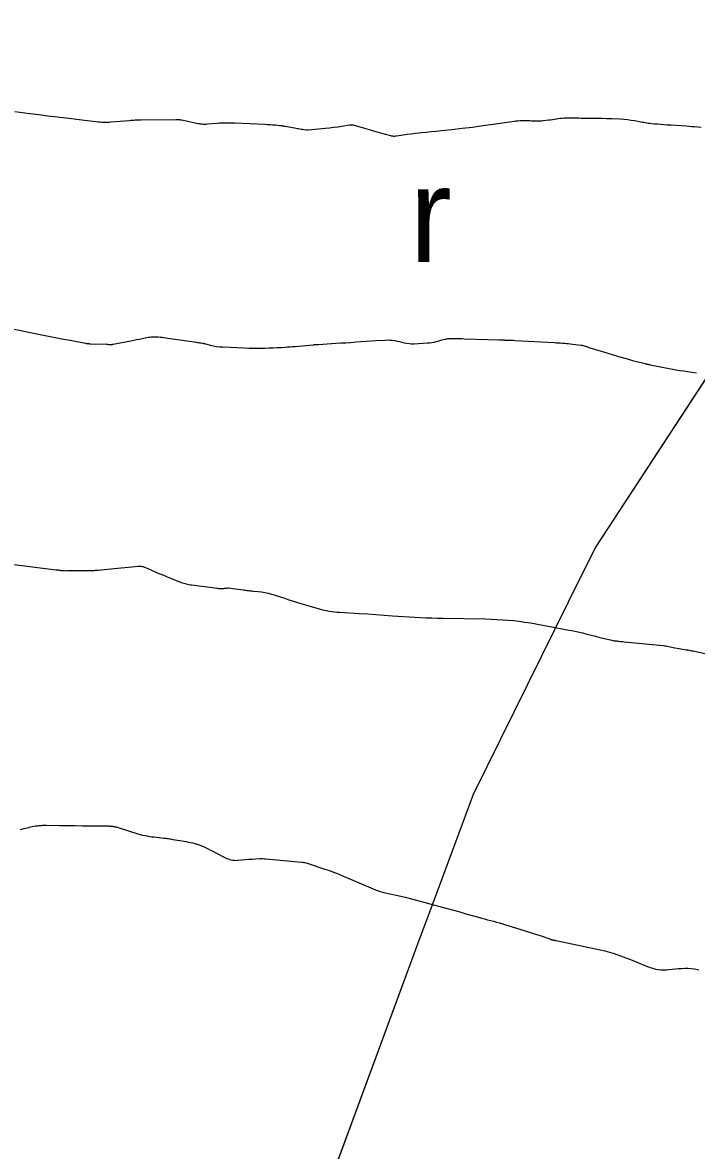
# Model space of a CAD drawing. Extents: x -629976 to -626966, y -1086511 to -1082952.
# Drawn here: x -628543.5 to -628393.8, y -1086175.2 to -1085924.7 of the extents above; entities that cross this region are included whole.
import ezdxf

# ---------------------------------------------------------------- set-up
doc = ezdxf.new("R2010")
doc.units = 0
for name, color, linetype in [('01_OBVOD PÚ', 7, 'Continuous'), ('01_SPRÁV_HRANICE', 7, 'Continuous'), ('01_VRSTEVNICE', 7, 'Continuous'), ('02_KULTURY STAV', 7, 'Continuous'), ('04_ZPF_OP_ORGAN', 7, 'Continuous')]:
    doc.layers.add(name, color=color, linetype=linetype)

msp = doc.modelspace()

# ---------------------------------------------------------------- linework, layer by layer
at = {"layer": '01_OBVOD PÚ'}
msp.add_lwpolyline([(-628341.94, -1085906.1), (-628364.43, -1085957.53), (-628376.86, -1085981.07), (-628416.21, -1086041.23), (-628422.26, -1086053.45), (-628443.41, -1086096.14), (-628453.2, -1086122.49), (-628455.25, -1086128.01), (-628487.12, -1086214.31), (-628510.82, -1086282.32), (-628525.65, -1086314.27), (-628531.32, -1086323.89), (-628534.4, -1086329.12), (-628536.6, -1086332.86), (-628546.36, -1086361.96)], dxfattribs=at)
at = {"layer": '01_SPRÁV_HRANICE'}
for p, q in [((-628376.86, -1085981.07), (-628416.21, -1086041.23)), ((-628416.21, -1086041.23), (-628422.26, -1086053.45)), ((-628422.26, -1086053.45), (-628443.41, -1086096.14)), ((-628443.41, -1086096.14), (-628453.2, -1086122.49)), ((-628453.2, -1086122.49), (-628455.25, -1086128.01)), ((-628455.25, -1086128.01), (-628487.12, -1086214.31))]:
    msp.add_line(p, q, dxfattribs=at)
at = {"layer": '01_VRSTEVNICE'}
for points in [[(-628545.25, -1085944.44), (-628541.9, -1085944.87), (-628539.89, -1085945.13), (-628537.88, -1085945.38), (-628535.86, -1085945.63), (-628533.85, -1085945.88), (-628529.77, -1085946.36), (-628529.15, -1085946.44), (-628528.52, -1085946.51), (-628527.9, -1085946.58), (-628527.27, -1085946.66), (-628526.73, -1085946.72), (-628526.37, -1085946.76), (-628526.02, -1085946.79), (-628525.67, -1085946.81), (-628525.31, -1085946.82), (-628524.96, -1085946.82), (-628524.61, -1085946.81), (-628524.25, -1085946.8), (-628523.9, -1085946.77), (-628519.77, -1085946.43), (-628519.45, -1085946.4), (-628519.13, -1085946.38), (-628518.8, -1085946.35), (-628518.48, -1085946.33), (-628518.16, -1085946.32), (-628517.84, -1085946.3), (-628517.51, -1085946.29), (-628517.19, -1085946.28), (-628509.5, -1085946.19), (-628509.33, -1085946.19), (-628509.17, -1085946.19), (-628509, -1085946.2), (-628508.83, -1085946.22), (-628508.67, -1085946.24), (-628508.5, -1085946.26), (-628508.34, -1085946.29), (-628508.17, -1085946.32), (-628504.85, -1085947.03), (-628504.55, -1085947.09), (-628504.26, -1085947.14), (-628503.96, -1085947.18), (-628503.65, -1085947.21), (-628503.35, -1085947.23), (-628503.05, -1085947.24), (-628502.75, -1085947.23), (-628502.45, -1085947.21), (-628500.25, -1085947.02), (-628499.76, -1085946.99), (-628499.28, -1085946.96), (-628498.79, -1085946.94), (-628498.3, -1085946.93), (-628497.81, -1085946.93), (-628497.32, -1085946.93), (-628496.84, -1085946.94), (-628496.35, -1085946.96), (-628489.68, -1085947.27), (-628489.09, -1085947.3), (-628488.5, -1085947.34), (-628487.91, -1085947.38), (-628487.33, -1085947.43), (-628486.47, -1085947.52), (-628486.31, -1085947.53), (-628486.15, -1085947.55), (-628486, -1085947.57), (-628485.84, -1085947.6), (-628485.68, -1085947.62), (-628485.53, -1085947.65), (-628485.37, -1085947.67), (-628485.21, -1085947.7), (-628482.27, -1085948.24), (-628481.96, -1085948.29), (-628481.65, -1085948.35), (-628481.33, -1085948.4), (-628481.02, -1085948.45), (-628480.51, -1085948.53), (-628480.45, -1085948.54), (-628480.4, -1085948.55), (-628480.34, -1085948.55), (-628480.29, -1085948.55), (-628480.23, -1085948.56), (-628480.17, -1085948.55), (-628480.12, -1085948.55), (-628480.06, -1085948.55), (-628476.29, -1085948.17), (-628475.35, -1085948.07), (-628474.42, -1085947.96), (-628473.48, -1085947.83), (-628472.55, -1085947.68), (-628470.89, -1085947.42), (-628470.79, -1085947.4), (-628470.69, -1085947.39), (-628470.59, -1085947.39), (-628470.48, -1085947.39), (-628470.38, -1085947.39), (-628470.28, -1085947.4), (-628470.18, -1085947.42), (-628470.08, -1085947.44), (-628467.56, -1085948.16), (-628466.54, -1085948.44), (-628465.53, -1085948.73), (-628464.51, -1085949.02), (-628463.5, -1085949.31), (-628461.8, -1085949.79), (-628461.63, -1085949.83), (-628461.47, -1085949.86), (-628461.3, -1085949.88), (-628461.13, -1085949.9), (-628460.96, -1085949.9), (-628460.79, -1085949.9), (-628460.62, -1085949.88), (-628460.45, -1085949.86), (-628458.98, -1085949.64), (-628458.08, -1085949.51), (-628457.17, -1085949.39), (-628456.26, -1085949.28), (-628455.35, -1085949.18), (-628454.96, -1085949.14), (-628453.85, -1085949.02), (-628452.75, -1085948.91), (-628451.64, -1085948.79), (-628450.54, -1085948.67), (-628448.16, -1085948.42), (-628445.86, -1085948.16), (-628443.57, -1085947.89), (-628441.28, -1085947.59), (-628438.99, -1085947.27), (-628434.31, -1085946.59), (-628433.88, -1085946.54), (-628433.44, -1085946.49), (-628433, -1085946.46), (-628432.55, -1085946.43), (-628432.11, -1085946.42), (-628431.67, -1085946.43), (-628431.23, -1085946.44), (-628430.79, -1085946.47), (-628430.54, -1085946.49), (-628430.21, -1085946.51), (-628429.87, -1085946.53), (-628429.54, -1085946.55), (-628429.2, -1085946.55), (-628428.87, -1085946.55), (-628428.53, -1085946.54), (-628428.2, -1085946.52), (-628427.87, -1085946.48), (-628426.61, -1085946.32), (-628426.18, -1085946.26), (-628425.76, -1085946.2), (-628425.33, -1085946.13), (-628424.91, -1085946.05), (-628424.48, -1085945.98), (-628424.05, -1085945.93), (-628423.63, -1085945.9), (-628423.2, -1085945.88), (-628422.13, -1085945.85), (-628421.6, -1085945.84), (-628421.07, -1085945.84), (-628420.55, -1085945.86), (-628420.02, -1085945.88), (-628419.49, -1085945.9), (-628418.97, -1085945.91), (-628418.44, -1085945.92), (-628417.91, -1085945.93), (-628416.85, -1085945.92), (-628415.79, -1085945.93), (-628414.73, -1085945.94), (-628413.68, -1085945.97), (-628412.62, -1085946.02), (-628410.77, -1085946.1), (-628409.95, -1085946.16), (-628409.13, -1085946.24), (-628408.31, -1085946.35), (-628407.5, -1085946.48), (-628406.5, -1085946.66), (-628406.17, -1085946.72), (-628405.83, -1085946.78), (-628405.5, -1085946.85), (-628405.17, -1085946.91), (-628404.84, -1085946.97), (-628404.5, -1085947.02), (-628404.17, -1085947.06), (-628403.83, -1085947.1), (-628403.11, -1085947.16), (-628402.41, -1085947.22), (-628401.71, -1085947.28), (-628401.01, -1085947.33), (-628400.32, -1085947.38), (-628399.45, -1085947.43), (-628398.31, -1085947.51), (-628397.18, -1085947.58), (-628396.05, -1085947.66), (-628394.91, -1085947.75), (-628394.18, -1085947.8), (-628392.74, -1085947.93)], [(-628553.31, -1085991.14), (-628540.34, -1085993.81), (-628538.5, -1085994.19), (-628536.66, -1085994.56), (-628534.82, -1085994.92), (-628532.97, -1085995.27), (-628529.56, -1085995.91), (-628529.42, -1085995.94), (-628529.27, -1085995.96), (-628529.13, -1085995.98), (-628528.98, -1085995.99), (-628528.84, -1085996.01), (-628528.69, -1085996.02), (-628528.55, -1085996.03), (-628528.4, -1085996.03), (-628524.86, -1085996.14), (-628524.66, -1085996.15), (-628524.47, -1085996.16), (-628524.28, -1085996.16), (-628524.08, -1085996.16), (-628523.81, -1085996.17), (-628523.75, -1085996.17), (-628523.7, -1085996.17), (-628523.64, -1085996.17), (-628523.58, -1085996.16), (-628523.53, -1085996.16), (-628523.47, -1085996.15), (-628523.42, -1085996.14), (-628523.37, -1085996.13), (-628519.48, -1085995.37), (-628518.83, -1085995.25), (-628518.19, -1085995.12), (-628517.55, -1085994.99), (-628516.91, -1085994.85), (-628516.31, -1085994.73), (-628515.97, -1085994.66), (-628515.62, -1085994.6), (-628515.28, -1085994.55), (-628514.93, -1085994.52), (-628514.58, -1085994.49), (-628514.23, -1085994.48), (-628513.88, -1085994.49), (-628513.53, -1085994.51), (-628513.4, -1085994.52), (-628512.99, -1085994.55), (-628512.57, -1085994.6), (-628512.16, -1085994.65), (-628511.75, -1085994.7), (-628504.91, -1085995.68), (-628504.67, -1085995.72), (-628504.43, -1085995.75), (-628504.18, -1085995.79), (-628503.94, -1085995.83), (-628503.58, -1085995.89), (-628503.52, -1085995.9), (-628503.46, -1085995.91), (-628503.4, -1085995.93), (-628503.34, -1085995.94), (-628503.28, -1085995.96), (-628503.22, -1085995.98), (-628503.16, -1085996), (-628503.1, -1085996.01), (-628501.83, -1085996.33), (-628501.14, -1085996.49), (-628500.44, -1085996.61), (-628499.73, -1085996.69), (-628499.02, -1085996.75), (-628494.21, -1085996.96), (-628493.15, -1085996.99), (-628492.09, -1085997.01), (-628491.03, -1085997.01), (-628489.97, -1085997), (-628489.73, -1085996.99), (-628488.79, -1085996.97), (-628487.85, -1085996.93), (-628486.91, -1085996.89), (-628485.97, -1085996.83), (-628485.19, -1085996.78), (-628484.64, -1085996.75), (-628484.09, -1085996.71), (-628483.54, -1085996.66), (-628482.99, -1085996.61), (-628478.92, -1085996.25), (-628478.82, -1085996.24), (-628478.72, -1085996.23), (-628478.63, -1085996.23), (-628478.53, -1085996.22), (-628478.52, -1085996.22), (-628478.43, -1085996.21), (-628478.33, -1085996.21), (-628478.24, -1085996.2), (-628478.14, -1085996.19), (-628478.05, -1085996.19), (-628477.95, -1085996.18), (-628477.86, -1085996.18), (-628477.76, -1085996.17), (-628473.93, -1085995.93), (-628472.8, -1085995.86), (-628471.68, -1085995.79), (-628470.56, -1085995.72), (-628469.44, -1085995.64), (-628468.31, -1085995.56), (-628467.19, -1085995.49), (-628466.07, -1085995.41), (-628464.95, -1085995.33), (-628463.04, -1085995.2), (-628462.49, -1085995.19), (-628461.94, -1085995.2), (-628461.39, -1085995.25), (-628460.85, -1085995.33), (-628460.84, -1085995.33), (-628460.3, -1085995.44), (-628459.77, -1085995.55), (-628459.23, -1085995.68), (-628458.7, -1085995.81), (-628458.17, -1085995.93), (-628457.63, -1085996.01), (-628457.09, -1085996.04), (-628456.54, -1085996.03), (-628453.57, -1085995.86), (-628453.07, -1085995.82), (-628452.58, -1085995.75), (-628452.09, -1085995.65), (-628451.61, -1085995.54), (-628451.32, -1085995.46), (-628450.98, -1085995.36), (-628450.64, -1085995.27), (-628450.3, -1085995.18), (-628449.96, -1085995.09), (-628449.71, -1085995.03), (-628449.49, -1085994.98), (-628449.27, -1085994.94), (-628449.04, -1085994.9), (-628448.81, -1085994.88), (-628448.59, -1085994.86), (-628448.36, -1085994.85), (-628448.13, -1085994.85), (-628447.9, -1085994.85), (-628447.36, -1085994.86), (-628446.87, -1085994.87), (-628446.37, -1085994.88), (-628445.87, -1085994.9), (-628445.37, -1085994.91), (-628437.63, -1085995.16), (-628437.32, -1085995.17), (-628437.02, -1085995.18), (-628436.71, -1085995.18), (-628436.4, -1085995.19), (-628436.33, -1085995.2), (-628436.06, -1085995.2), (-628435.79, -1085995.21), (-628435.52, -1085995.22), (-628435.25, -1085995.23), (-628434.98, -1085995.24), (-628434.71, -1085995.26), (-628434.44, -1085995.27), (-628434.17, -1085995.28), (-628425.31, -1085995.77), (-628424.87, -1085995.8), (-628424.44, -1085995.82), (-628424, -1085995.86), (-628423.56, -1085995.89), (-628423.13, -1085995.93), (-628422.69, -1085995.97), (-628422.26, -1085996.01), (-628421.82, -1085996.06), (-628419.44, -1085996.32), (-628419.4, -1085996.33), (-628419.37, -1085996.33), (-628419.34, -1085996.34), (-628419.31, -1085996.34), (-628419.28, -1085996.35), (-628419.24, -1085996.36), (-628419.21, -1085996.37), (-628419.18, -1085996.38), (-628418.74, -1085996.51), (-628418.48, -1085996.59), (-628418.23, -1085996.67), (-628417.98, -1085996.75), (-628417.73, -1085996.83), (-628413.71, -1085998.08), (-628412.27, -1085998.51), (-628410.84, -1085998.93), (-628409.4, -1085999.33), (-628407.96, -1085999.72), (-628405.18, -1086000.44), (-628405.12, -1086000.46), (-628405.06, -1086000.47), (-628405, -1086000.49), (-628404.94, -1086000.5), (-628404.88, -1086000.51), (-628404.82, -1086000.53), (-628404.76, -1086000.54), (-628404.7, -1086000.55), (-628404.57, -1086000.58), (-628404.44, -1086000.61), (-628404.31, -1086000.64), (-628404.18, -1086000.67), (-628404.06, -1086000.69), (-628399.86, -1086001.53), (-628399.06, -1086001.69), (-628398.26, -1086001.83), (-628397.45, -1086001.96), (-628396.64, -1086002.07), (-628393.75, -1086002.47)], [(-628553.78, -1086044), (-628536.03, -1086046.22), (-628535.89, -1086046.24), (-628535.75, -1086046.26), (-628535.61, -1086046.28), (-628535.47, -1086046.31), (-628535.33, -1086046.33), (-628535.2, -1086046.35), (-628535.06, -1086046.37), (-628534.92, -1086046.39), (-628534.83, -1086046.4), (-628534.65, -1086046.42), (-628534.47, -1086046.43), (-628534.28, -1086046.43), (-628534.1, -1086046.44), (-628533.72, -1086046.43), (-628533.35, -1086046.42), (-628532.98, -1086046.42), (-628532.6, -1086046.42), (-628532.23, -1086046.41), (-628528.43, -1086046.39), (-628528.21, -1086046.38), (-628527.99, -1086046.38), (-628527.78, -1086046.37), (-628527.56, -1086046.36), (-628527.35, -1086046.34), (-628527.13, -1086046.33), (-628526.91, -1086046.31), (-628526.7, -1086046.29), (-628522.42, -1086045.86), (-628521.63, -1086045.78), (-628520.83, -1086045.7), (-628520.04, -1086045.63), (-628519.24, -1086045.56), (-628517.82, -1086045.45), (-628517.74, -1086045.44), (-628517.65, -1086045.43), (-628517.57, -1086045.43), (-628517.49, -1086045.42), (-628517.4, -1086045.42), (-628517.32, -1086045.43), (-628517.24, -1086045.44), (-628517.15, -1086045.45), (-628516.95, -1086045.5), (-628516.77, -1086045.54), (-628516.59, -1086045.6), (-628516.42, -1086045.66), (-628516.24, -1086045.73), (-628514.91, -1086046.31), (-628514.07, -1086046.68), (-628513.23, -1086047.03), (-628512.38, -1086047.38), (-628511.53, -1086047.72), (-628508.26, -1086049.03), (-628507.98, -1086049.13), (-628507.71, -1086049.22), (-628507.43, -1086049.3), (-628507.15, -1086049.38), (-628506.86, -1086049.44), (-628506.57, -1086049.5), (-628506.29, -1086049.55), (-628506, -1086049.59), (-628500.24, -1086050.35), (-628500.02, -1086050.37), (-628499.79, -1086050.39), (-628499.57, -1086050.39), (-628499.35, -1086050.39), (-628499.13, -1086050.38), (-628498.91, -1086050.37), (-628498.69, -1086050.35), (-628498.47, -1086050.32), (-628498.41, -1086050.31), (-628498.16, -1086050.29), (-628497.91, -1086050.27), (-628497.67, -1086050.28), (-628497.42, -1086050.31), (-628494.47, -1086050.71), (-628494.19, -1086050.74), (-628493.91, -1086050.78), (-628493.62, -1086050.81), (-628493.34, -1086050.85), (-628493.05, -1086050.88), (-628492.77, -1086050.91), (-628492.48, -1086050.94), (-628492.2, -1086050.97), (-628491.19, -1086051.06), (-628490.43, -1086051.15), (-628489.67, -1086051.27), (-628488.93, -1086051.44), (-628488.18, -1086051.63), (-628488.16, -1086051.64), (-628487.43, -1086051.85), (-628486.71, -1086052.08), (-628485.99, -1086052.31), (-628485.28, -1086052.56), (-628484.56, -1086052.81), (-628483.85, -1086053.05), (-628483.13, -1086053.28), (-628482.4, -1086053.5), (-628477.65, -1086054.89), (-628477.09, -1086055.05), (-628476.53, -1086055.19), (-628475.96, -1086055.3), (-628475.38, -1086055.41), (-628474.81, -1086055.49), (-628474.23, -1086055.56), (-628473.65, -1086055.62), (-628473.07, -1086055.66), (-628468.76, -1086055.93), (-628466.9, -1086056.05), (-628465.04, -1086056.17), (-628463.18, -1086056.3), (-628461.32, -1086056.43), (-628460.11, -1086056.52), (-628458.86, -1086056.61), (-628457.6, -1086056.69), (-628456.35, -1086056.76), (-628455.09, -1086056.83), (-628453.84, -1086056.88), (-628452.58, -1086056.93), (-628451.33, -1086056.96), (-628450.07, -1086056.99), (-628440.64, -1086057.16), (-628439.39, -1086057.2), (-628438.14, -1086057.25), (-628436.9, -1086057.32), (-628435.65, -1086057.4), (-628434.4, -1086057.52), (-628433.16, -1086057.66), (-628431.92, -1086057.84), (-628430.69, -1086058.05), (-628422.08, -1086059.63), (-628421.09, -1086059.82), (-628420.11, -1086060.03), (-628419.13, -1086060.26), (-628418.15, -1086060.5), (-628417.18, -1086060.76), (-628416.2, -1086061.01), (-628415.23, -1086061.25), (-628414.25, -1086061.48), (-628412.55, -1086061.89), (-628412.39, -1086061.92), (-628412.23, -1086061.95), (-628412.06, -1086061.98), (-628411.9, -1086062.01), (-628411.74, -1086062.03), (-628411.58, -1086062.05), (-628411.41, -1086062.07), (-628411.25, -1086062.09), (-628411, -1086062.11), (-628410.71, -1086062.13), (-628410.42, -1086062.16), (-628410.13, -1086062.18), (-628409.84, -1086062.21), (-628401.21, -1086063.08), (-628400.88, -1086063.12), (-628400.55, -1086063.16), (-628400.23, -1086063.22), (-628399.91, -1086063.29), (-628399.59, -1086063.36), (-628399.26, -1086063.43), (-628398.94, -1086063.5), (-628398.62, -1086063.56), (-628397.62, -1086063.74), (-628397.24, -1086063.8), (-628396.85, -1086063.87), (-628396.46, -1086063.93), (-628396.07, -1086063.99), (-628395.69, -1086064.05), (-628395.3, -1086064.12), (-628394.92, -1086064.2), (-628394.53, -1086064.27), (-628391.31, -1086064.98)], [(-628544.02, -1086103.92), (-628543.14, -1086103.71), (-628542.12, -1086103.45), (-628541.76, -1086103.36), (-628541.4, -1086103.28), (-628541.03, -1086103.21), (-628540.66, -1086103.14), (-628540.49, -1086103.11), (-628540.21, -1086103.07), (-628539.93, -1086103.04), (-628539.65, -1086103.01), (-628539.36, -1086103), (-628539.08, -1086102.99), (-628538.79, -1086102.98), (-628538.51, -1086102.98), (-628538.22, -1086102.98), (-628535.36, -1086103.01), (-628533.64, -1086103.03), (-628531.92, -1086103.05), (-628530.21, -1086103.07), (-628528.49, -1086103.09), (-628525.33, -1086103.13), (-628525.17, -1086103.13), (-628525, -1086103.13), (-628524.84, -1086103.13), (-628524.68, -1086103.13), (-628524.52, -1086103.14), (-628524.36, -1086103.14), (-628524.2, -1086103.15), (-628524.03, -1086103.16), (-628523.93, -1086103.17), (-628523.72, -1086103.19), (-628523.51, -1086103.21), (-628523.3, -1086103.24), (-628523.09, -1086103.29), (-628523.01, -1086103.3), (-628522.76, -1086103.36), (-628522.51, -1086103.42), (-628522.27, -1086103.49), (-628522.03, -1086103.57), (-628517.89, -1086104.87), (-628517.39, -1086105.01), (-628516.88, -1086105.15), (-628516.38, -1086105.26), (-628515.86, -1086105.36), (-628515.35, -1086105.44), (-628514.84, -1086105.52), (-628514.32, -1086105.58), (-628513.8, -1086105.64), (-628512.14, -1086105.81), (-628511.89, -1086105.83), (-628511.64, -1086105.87), (-628511.39, -1086105.9), (-628511.14, -1086105.94), (-628510.89, -1086105.98), (-628510.64, -1086106.03), (-628510.39, -1086106.07), (-628510.14, -1086106.11), (-628508.59, -1086106.37), (-628508.11, -1086106.45), (-628507.63, -1086106.53), (-628507.16, -1086106.62), (-628506.68, -1086106.7), (-628506.2, -1086106.79), (-628505.73, -1086106.9), (-628505.27, -1086107.03), (-628504.8, -1086107.17), (-628504.76, -1086107.18), (-628504.28, -1086107.35), (-628503.8, -1086107.53), (-628503.33, -1086107.72), (-628502.87, -1086107.93), (-628502.76, -1086107.98), (-628502.25, -1086108.23), (-628501.74, -1086108.48), (-628501.23, -1086108.73), (-628500.73, -1086109), (-628498.47, -1086110.18), (-628498.15, -1086110.33), (-628497.83, -1086110.46), (-628497.5, -1086110.57), (-628497.16, -1086110.66), (-628496.82, -1086110.73), (-628496.47, -1086110.76)], [(-628496.47, -1086110.76), (-628496.13, -1086110.77), (-628495.78, -1086110.75), (-628494.85, -1086110.66), (-628494.06, -1086110.59), (-628493.27, -1086110.53), (-628492.48, -1086110.48), (-628491.69, -1086110.43), (-628490.77, -1086110.39), (-628490.44, -1086110.38), (-628490.12, -1086110.38), (-628489.79, -1086110.4), (-628489.46, -1086110.42), (-628481.46, -1086111.18), (-628481.23, -1086111.2), (-628481, -1086111.24), (-628480.77, -1086111.28), (-628480.54, -1086111.33), (-628480.32, -1086111.39), (-628480.09, -1086111.46), (-628479.87, -1086111.52), (-628479.65, -1086111.6), (-628476.8, -1086112.57), (-628476.33, -1086112.73), (-628475.87, -1086112.89), (-628475.4, -1086113.05), (-628474.93, -1086113.21), (-628474.47, -1086113.38), (-628474.01, -1086113.55), (-628473.55, -1086113.73), (-628473.09, -1086113.92), (-628465.12, -1086117.29), (-628464.85, -1086117.39), (-628464.59, -1086117.5), (-628464.32, -1086117.6), (-628464.04, -1086117.69), (-628463.77, -1086117.77), (-628463.5, -1086117.85), (-628463.22, -1086117.92), (-628462.94, -1086117.99), (-628460.17, -1086118.6), (-628458.5, -1086118.98), (-628456.84, -1086119.38), (-628455.19, -1086119.81), (-628453.54, -1086120.25), (-628449.14, -1086121.46), (-628447.77, -1086121.85), (-628446.39, -1086122.23), (-628445.01, -1086122.62), (-628443.63, -1086123.01), (-628442.21, -1086123.41), (-628441.54, -1086123.6), (-628440.88, -1086123.78), (-628440.21, -1086123.96), (-628439.54, -1086124.13), (-628438.88, -1086124.3), (-628438.21, -1086124.48), (-628437.55, -1086124.67), (-628436.89, -1086124.87), (-628431.87, -1086126.4), (-628430.92, -1086126.7), (-628429.96, -1086127), (-628429.02, -1086127.32), (-628428.07, -1086127.64), (-628426.38, -1086128.24), (-628426.28, -1086128.27), (-628426.18, -1086128.3), (-628426.09, -1086128.33), (-628425.99, -1086128.36), (-628425.89, -1086128.39), (-628425.79, -1086128.42), (-628425.69, -1086128.44), (-628425.59, -1086128.46), (-628425.53, -1086128.47), (-628425.39, -1086128.5), (-628425.26, -1086128.52), (-628425.13, -1086128.55), (-628424.99, -1086128.58), (-628416.24, -1086130.4), (-628414.16, -1086130.9), (-628412.09, -1086131.48), (-628410.07, -1086132.17), (-628408.07, -1086132.95), (-628405.26, -1086134.13), (-628404.68, -1086134.36), (-628404.09, -1086134.57), (-628403.49, -1086134.75), (-628402.89, -1086134.92), (-628402.27, -1086135.03), (-628401.66, -1086135.11), (-628401.04, -1086135.12), (-628400.42, -1086135.09), (-628399.87, -1086135.03), (-628399.17, -1086134.96), (-628398.46, -1086134.89), (-628397.76, -1086134.83), (-628397.06, -1086134.77), (-628396.35, -1086134.75), (-628395.65, -1086134.75), (-628394.95, -1086134.81), (-628394.25, -1086134.9), (-628393.27, -1086135.06)]]:
    msp.add_lwpolyline(points, dxfattribs=at)
at = {"layer": '02_KULTURY STAV'}
msp.add_lwpolyline([(-628341.94, -1085906.1), (-628364.43, -1085957.53), (-628376.86, -1085981.07), (-628416.21, -1086041.23), (-628422.26, -1086053.45), (-628443.41, -1086096.14), (-628453.2, -1086122.49), (-628455.25, -1086128.01), (-628487.12, -1086214.31), (-628510.82, -1086282.32), (-628525.65, -1086314.27), (-628531.32, -1086323.89), (-628534.4, -1086329.12), (-628536.6, -1086332.86), (-628544.68, -1086356.94)], dxfattribs=at)
at = {"layer": '04_ZPF_OP_ORGAN'}
msp.add_lwpolyline([(-628341.94, -1085906.1), (-628364.43, -1085957.53), (-628376.86, -1085981.07), (-628416.21, -1086041.23), (-628422.26, -1086053.45), (-628443.41, -1086096.14), (-628453.2, -1086122.49), (-628455.25, -1086128.01), (-628487.12, -1086214.31), (-628510.82, -1086282.32), (-628525.65, -1086314.27), (-628531.32, -1086323.89), (-628534.4, -1086329.12), (-628536.6, -1086332.86), (-628544.67, -1086356.94)], dxfattribs=at)

# ---------------------------------------------------------------- texts
at = {"layer": '02_KULTURY STAV'}
msp.add_text('r', height=21, dxfattribs=at).set_placement((-628457.54, -1085977.86))

doc.saveas('drawing.dxf')
